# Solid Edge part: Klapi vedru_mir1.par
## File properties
Author: Türk
Template: Iso Part.par
Last saved by: Türk
Revision: 2
Application: Solid Edge
Density: 7833,000 kg/m^3
Accuracy: 0,990
Username: Türk
Material: Steel
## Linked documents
Klapi vedru_mir.par
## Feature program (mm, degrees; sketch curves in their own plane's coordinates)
part copy "CopiedPart_1"
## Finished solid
Body 1: solid body, 3 faces, 2 edges, 0 vertices.
  Faces by surface: plane 2, spline 1
  Edges by curve: intersection 2
Bounding box of the edges (mm; curved faces can reach further): 17.000 x 19.333 x 18.336, from (0, -9.6667, -9.6664) to (17, 9.6665, 8.6699).
Planar faces by outward normal: +x 1, -x 1
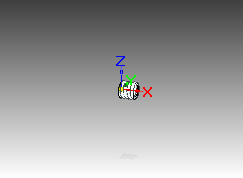
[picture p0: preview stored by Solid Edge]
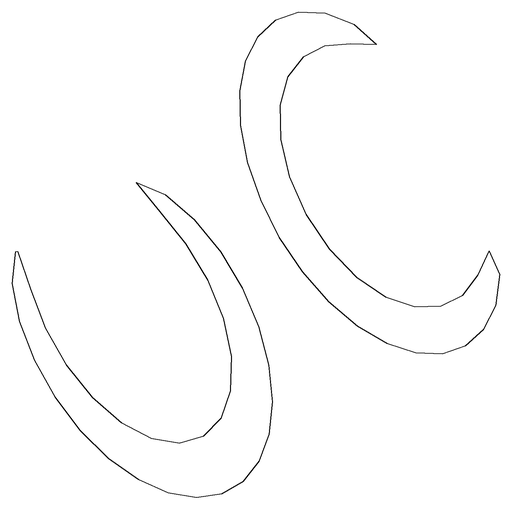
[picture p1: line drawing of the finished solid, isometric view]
